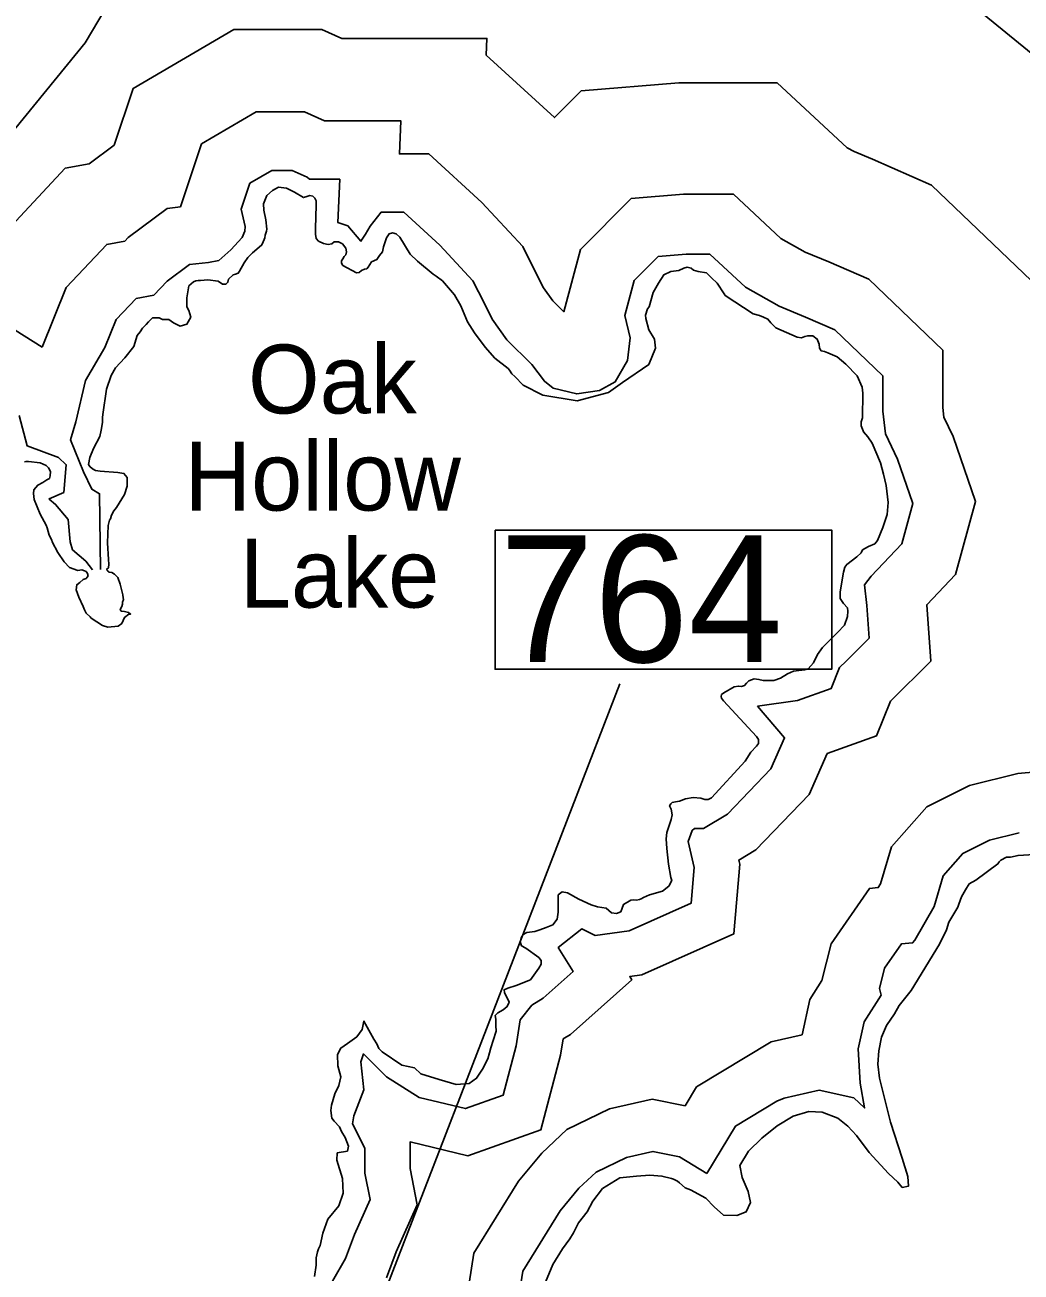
# Model space of a CAD drawing. Extents: x 1662474 to 1856135, y 779280 to 917889.
# Drawn here: x 1704529 to 1707278, y 822946 to 826386 of the extents above; entities that cross this region are included whole.
import ezdxf

# ---------------------------------------------------------------- set-up
doc = ezdxf.new("R2010")
doc.units = 0
for name, color, linetype in [('Exist Hydrographic Lake Shore', 7, 'Continuous'), ('Exist Hydrographic Lake Shore Label', 7, 'Continuous'), ('Old_Level_44', 7, 'Continuous'), ('Scratch_Level_2', 7, 'Continuous')]:
    doc.layers.add(name, color=color, linetype=linetype)

msp = doc.modelspace()

# ---------------------------------------------------------------- linework, layer by layer
at = {"layer": 'Exist Hydrographic Lake Shore'}
for points in [[(1706250.5, 825545.1), (1706266.8, 825519.9), (1706269.1, 825495), (1706251, 825449.6), (1706178.4, 825399.8), (1706139.8, 825372.4), (1706053.4, 825349.6), (1705958.4, 825365.4), (1705903.8, 825392.7), (1705881.2, 825416.8), (1705872.6, 825423.4), (1705866.5, 825434.1), (1705862.9, 825438.3), (1705825.4, 825467.2), (1705799.4, 825497.1), (1705769.8, 825536.5), (1705750.8, 825566.9), (1705732.1, 825611.8), (1705714.6, 825641.8), (1705681.2, 825680.1), (1705663.9, 825693.4), (1705656, 825698.7), (1705612.5, 825734.4), (1705592, 825754.3), (1705563.9, 825800.8), (1705553.1, 825810), (1705543.8, 825812.9), (1705534.2, 825810.2), (1705527.1, 825798.9), (1705519, 825774.2), (1705515.6, 825760.4), (1705507.5, 825749.9), (1705500.6, 825739.4), (1705485.8, 825732.6), (1705480.5, 825725.4), (1705476.5, 825718.4), (1705472.4, 825713.9), (1705465.8, 825712.3), (1705457.6, 825708.9), (1705451, 825703.4), (1705444.5, 825702.6), (1705406.5, 825722.8), (1705402.5, 825729.1), (1705402.5, 825735.9), (1705406.5, 825740.7), (1705410.4, 825747.5), (1705414.6, 825752.2), (1705416.1, 825760.4), (1705414.6, 825770.9), (1705405.4, 825782.7), (1705394.4, 825787.9), (1705382.5, 825787.9), (1705375.8, 825782.9), (1705366, 825781.1), (1705352.6, 825783.2), (1705339.5, 825789.5), (1705332.4, 825796.9), (1705331.1, 825809.4), (1705330.6, 825823.6), (1705330.6, 825836.5), (1705331.6, 825844.9), (1705332.4, 825901.3), (1705328.8, 825908.4), (1705323.2, 825914.2), (1705315.4, 825915.5), (1705307.2, 825913.4), (1705297.5, 825910), (1705273.4, 825924.7), (1705250.5, 825936.5), (1705229, 825938.8), (1705211.8, 825929.9), (1705196.5, 825916), (1705187, 825892.6), (1705188.6, 825875.1), (1705194.1, 825849.1), (1705196.5, 825823.4), (1705195.6, 825817.6), (1705191.8, 825806.3), (1705190.8, 825799.2), (1705184.6, 825783.4), (1705182, 825778.5), (1705156.6, 825758), (1705144.2, 825745.1), (1705134.5, 825730.2), (1705121.1, 825706.8), (1705117.5, 825701.8), (1705110.4, 825698.4), (1705103.5, 825696.6), (1705090.5, 825684.8), (1705089.1, 825676.6), (1705083.6, 825670.9), (1705073.9, 825671.1), (1705062.4, 825679.2), (1705033.5, 825683.2), (1705013.8, 825681.1), (1705006.8, 825681.6), (1705000.4, 825680.6), (1704994.4, 825677.2), (1704981.2, 825666.4), (1704976.2, 825633.6)], [(1706553.9, 824403.7), (1706553.9, 824415.2), (1706548.4, 824423.6), (1706457.1, 824522.1), (1706451.2, 824529.2), (1706450, 824533.6), (1706451.2, 824539.1), (1706458.1, 824544.1), (1706486.5, 824560.4), (1706498.2, 824562.5), (1706506.4, 824561.7), (1706514.9, 824563.8), (1706520.1, 824570.6), (1706526.6, 824576.7), (1706541.9, 824582.2), (1706554.5, 824580.9), (1706566.8, 824577.7), (1706589.1, 824577.4), (1706595.6, 824577.7), (1706614.2, 824583.8), (1706633.2, 824596.4), (1706649.8, 824603.4), (1706680.1, 824606.9), (1706690.9, 824610.2), (1706704.9, 824626.8), (1706716.6, 824649.6), (1706730, 824669.3), (1706758.9, 824697.7), (1706771.8, 824709.8), (1706790.9, 824730.8), (1706798.8, 824754.1), (1706800.1, 824769.3), (1706798.8, 824778.5), (1706788, 824790.1), (1706778.6, 824803.9), (1706778.6, 824822.6), (1706788, 824876.9), (1706792, 824890.1), (1706797.2, 824897.9), (1706824.5, 824918.6), (1706836.4, 824930.2), (1706840.8, 824938.3), (1706856.8, 824947.8), (1706874.1, 824954.9), (1706882.2, 824963.8), (1706896.5, 825000), (1706909, 825035.7), (1706911.6, 825069.3), (1706905.4, 825115.8), (1706898.2, 825147.2), (1706890.1, 825178.5), (1706867.2, 825232.8), (1706855.5, 825250.1), (1706843.1, 825263.8), (1706842.6, 825266.9), (1706837.1, 825280.3), (1706837.1, 825291.4), (1706840.8, 825302.1), (1706841.6, 825370.9), (1706839.2, 825386.9), (1706825.6, 825418.1), (1706794.6, 825450.7), (1706770.5, 825470.4), (1706745, 825481.9), (1706735.5, 825485.3), (1706726.1, 825487.4), (1706721.9, 825494.5), (1706720.6, 825506.1), (1706715.4, 825519.9), (1706703, 825529.1), (1706689.6, 825529.1), (1706681.5, 825527.1), (1706672, 825523.4), (1706659.8, 825524.7), (1706600.9, 825551.2), (1706587.2, 825564.1), (1706579.4, 825574.3), (1706567, 825580.1), (1706556.2, 825584.8), (1706538.8, 825589.5), (1706461.8, 825640.4), (1706458.6, 825644.1), (1706439.2, 825674), (1706424.2, 825689), (1706409.6, 825702.6), (1706386.8, 825706.3), (1706374.4, 825709.7), (1706367.6, 825715.8), (1706356.9, 825717.9), (1706347.4, 825715.8), (1706333.8, 825708.7), (1706311.4, 825706.1), (1706292.2, 825697.1), (1706277.2, 825673.8), (1706262.9, 825648.3), (1706252.1, 825608.7), (1706247.1, 825602.9), (1706241.6, 825585.6), (1706242.6, 825576.4), (1706250.5, 825545.1)], [(1704976.2, 825633.6), (1704976.2, 825608.9), (1704981.2, 825598.2), (1704986.5, 825580.3), (1704976.2, 825560.6), (1704957.1, 825554.9), (1704939.2, 825564.6), (1704926.1, 825574), (1704908.9, 825573.5), (1704899.4, 825578.8), (1704881.5, 825577.9), (1704870.2, 825566.9), (1704863.9, 825559.6), (1704853.4, 825550.1), (1704846.6, 825539.6), (1704838.8, 825529.4), (1704829.2, 825499.5), (1704804.9, 825468), (1704779.4, 825440.2), (1704767.1, 825419.4), (1704753.8, 825381.1), (1704744, 825311.6), (1704743.2, 825303.2), (1704743.2, 825289.2), (1704739.5, 825268.2), (1704735.9, 825251.2), (1704718, 825217.9), (1704707.8, 825193.2), (1704704.6, 825173.8), (1704708.5, 825167.8), (1704715.6, 825161.9), (1704723.8, 825157.5), (1704737.1, 825154.9), (1704785.5, 825151.4), (1704802, 825149.1), (1704811.1, 825137.6), (1704811.1, 825114.2), (1704804.1, 825091.1), (1704781.5, 825055.1), (1704774.1, 825045.9), (1704767.9, 825034.1), (1704764.8, 825024.2), (1704762.6, 825020.5), (1704758.4, 825005.2), (1704756.9, 824958), (1704760, 824911.6), (1704761, 824898.7), (1704760, 824888.8), (1704754.8, 824885.1), (1704756, 824880.9), (1704757.6, 824879), (1704760, 824878.2), (1704761, 824876.7), (1704769.1, 824875.6), (1704776, 824871.1), (1704785.2, 824861.7), (1704792, 824843.3), (1704798.9, 824814.2), (1704800.4, 824805.8), (1704800.6, 824801.1), (1704798.4, 824793.8), (1704798, 824788.8), (1704796, 824781.6), (1704792, 824773.8), (1704794.6, 824769.1), (1704803.9, 824768), (1704814.9, 824765.4), (1704820.4, 824760.9), (1704816.1, 824760.9), (1704803.9, 824752), (1704796, 824735.4), (1704786.5, 824727.3), (1704758.1, 824724.9), (1704743.5, 824729.4), (1704712.2, 824749.4), (1704709.4, 824753.3), (1704698.4, 824763.6), (1704693.4, 824772.4), (1704689.4, 824782.2), (1704677.6, 824807.4), (1704670.5, 824828.4), (1704672.1, 824842), (1704680.2, 824847.8), (1704689.6, 824856.2), (1704698, 824859.3), (1704703.2, 824866.4), (1704701.8, 824873), (1704698, 824878.2), (1704693.6, 824880.1), (1704685.8, 824882.7), (1704674.8, 824881.6), (1704651.9, 824889.8), (1704637.4, 824904.8), (1704619.9, 824931.2), (1704604.6, 824960.1), (1704602.8, 824965.4), (1704596, 824979), (1704590.1, 824998.9), (1704587.2, 825006.8), (1704571.2, 825037)], [(1704571.2, 825037), (1704554.8, 825077.4), (1704552.4, 825093.7), (1704554, 825103.9), (1704564.2, 825117.1), (1704578.1, 825123.9), (1704589.9, 825131), (1704596.8, 825135.4), (1704598.6, 825142.6), (1704599.6, 825154.1), (1704594.1, 825164.3), (1704587.2, 825171.4), (1704571.2, 825178.5), (1704539, 825181.9), (1704531.4, 825181.6), (1704527.5, 825180.9)], [(1706532.1, 824380.3), (1706548.4, 824396.9), (1706553.9, 824403.7)], [(1705376, 823370.1), (1705373.4, 823391.9), (1705375.2, 823406.6), (1705383.9, 823437.8), (1705395.4, 823460.7), (1705400.9, 823484.1), (1705393, 823515.2), (1705391.2, 823546), (1705400.9, 823563.8), (1705419.6, 823576.4), (1705445.2, 823595.1), (1705459.5, 823615.2), (1705464.5, 823638.1), (1705491.5, 823588.2), (1705500.1, 823575.6), (1705505.9, 823562.8), (1705514.9, 823553.1), (1705569.1, 823516.3), (1705604.1, 823509.5), (1705621.9, 823492.9), (1705672, 823476.9), (1705719, 823463.1), (1705755, 823466.2), (1705775.5, 823480.6), (1705792, 823505.3), (1705806.1, 823533.9), (1705811.1, 823550.4), (1705814.6, 823564.4), (1705821.4, 823584.3), (1705829.2, 823610.6), (1705828.2, 823626), (1705828.2, 823643.1), (1705826.6, 823653.6), (1705834.5, 823661.4), (1705848.8, 823669.3), (1705860, 823678.2), (1705865.2, 823690.3), (1705852.1, 823717.4), (1705851.4, 823724.7), (1705861.5, 823729.4), (1705884.4, 823736.2), (1705924.2, 823752), (1705947.1, 823783.8), (1705953.4, 823795.3), (1705953.4, 823805.3), (1705947.1, 823813.9), (1705911.1, 823839.7), (1705899.6, 823846.2), (1705895.9, 823857.2), (1705898.5, 823868.2), (1705903.8, 823876.9), (1705914, 823883), (1705936.4, 823885.6), (1705950.2, 823889.8), (1705967.6, 823896.4), (1705986, 823904.2), (1705998.2, 823919.4), (1706000.9, 823938.6), (1706000.9, 823986.4), (1706011.4, 823995.1), (1706026.4, 823991.9), (1706058.1, 823974.3), (1706091.8, 823958.8), (1706109.4, 823953.8), (1706133, 823949.9), (1706148.1, 823937.3), (1706161.8, 823935.2), (1706173.4, 823939.9), (1706181.2, 823959.9), (1706201.5, 823972.2), (1706209, 823972.8), (1706217.2, 823971.9), (1706224.8, 823973.2), (1706229.8, 823975.6), (1706235.9, 823979.6), (1706252.9, 823986.6), (1706288.6, 823996.4), (1706305.6, 824010), (1706314.2, 824025.8), (1706311.1, 824034.7), (1706305.4, 824071.2), (1706300.1, 824114.8), (1706299.1, 824141.2), (1706300.4, 824158.8), (1706312.5, 824194.8), (1706315.1, 824207.6), (1706312.5, 824222.9), (1706308.2, 824231.8), (1706311.4, 824237.8), (1706315.1, 824241.2), (1706324.5, 824243.3), (1706335.2, 824244.9), (1706351.6, 824251.8), (1706372.9, 824255.1), (1706394.6, 824253.1), (1706405.4, 824249.4), (1706414.5, 824249.4), (1706424.2, 824254.1), (1706517.1, 824354.9), (1706532.1, 824380.3)], [(1707358.9, 824100.8), (1707269.9, 824095.1), (1707248.6, 824090.3), (1707237.6, 824090.3), (1707222.6, 824082.4), (1707218, 824078), (1707214, 824071.9), (1707153.1, 824026.6), (1707135.2, 824016.6), (1707125, 824000.3), (1707113.5, 823980.6), (1707106.1, 823960.7), (1707103.5, 823952.2), (1707089.4, 823929.7), (1707079.1, 823910.8), (1707072.2, 823889.8), (1707053.4, 823850.7), (1706975.1, 823722.9), (1706941.9, 823681.4), (1706929, 823658.3), (1706906.4, 823626.3), (1706893.2, 823594), (1706885.4, 823555.7), (1706882.8, 823519.2), (1706887.8, 823480.6), (1706917.4, 823359.1), (1706950.2, 823259.6), (1706966, 823209.5), (1706967, 823182.4), (1706950.2, 823179.3), (1706937.9, 823194), (1706912.5, 823217.4), (1706858.6, 823275.6)], [(1706858.6, 823275.6), (1706824, 823322.4), (1706799.9, 823348.3), (1706772.5, 823370.6), (1706729.2, 823387.2), (1706692.2, 823389), (1706649.2, 823375.6), (1706605.4, 823348.9), (1706563.1, 823315.6), (1706525.9, 823279.1), (1706501.8, 823239.9), (1706508.2, 823206.4), (1706525, 823167.8), (1706531.1, 823137.6), (1706519.5, 823112.1), (1706494.1, 823102.1), (1706457.1, 823102.9), (1706431.6, 823125.5), (1706408, 823149.9), (1706365.8, 823172.8), (1706351, 823178.5), (1706335.2, 823192.2), (1706329.8, 823196.4), (1706319.2, 823202.4), (1706313.8, 823204.2), (1706286.8, 823210.8), (1706253.6, 823212.9), (1706216.4, 823210.8), (1706170.5, 823206.1), (1706123, 823176.2), (1706096.5, 823141.8), (1706080.8, 823111.9), (1706056.5, 823081.9), (1706043.1, 823054.4), (1706033, 823037.9), (1706013, 823009.5), (1705986.2, 822966.4), (1705965.8, 822918.4)], [(1705328.2, 822933.4), (1705333.2, 822964.6), (1705333.2, 822985.1), (1705336.6, 823001.4), (1705339.5, 823010.3), (1705344, 823018.9), (1705351.4, 823053.3), (1705364.5, 823092.2), (1705395.1, 823128.9), (1705407.5, 823163.3), (1705405.1, 823204.2), (1705390.1, 823254.4), (1705391, 823274.3), (1705419.2, 823279.8), (1705421.9, 823293.5), (1705413, 823317.4), (1705403, 823333.6), (1705397.5, 823346.2), (1705382.5, 823362.2), (1705376, 823370.1)]]:
    msp.add_lwpolyline(points, dxfattribs=at)
at = {"layer": 'Old_Level_44'}
msp.add_line((1706604.2, 823417.4), (1706624.5, 823425.6), dxfattribs=at)
for points in [[(1706416.7, 828453.3), (1706394.4, 828185.5), (1706206.4, 827887), (1705933.6, 827714.4), (1705493.1, 827597.8), (1705428.1, 827536.3), (1705411.4, 827514), (1705562.9, 827305.8), (1705253, 826872.2), (1704944.5, 826583.1), (1704843.4, 826587.3), (1704694.9, 826337.4), (1704445.7, 826032.9), (1704213.1, 825950.9), (1704071.6, 825880.8), (1703834.3, 825734.9), (1703563.6, 825780), (1703448, 825768.5), (1703249, 825751.6), (1703132.7, 825730.4)], [(1708420, 826265.1), (1708349.1, 826265.1), (1708347.7, 826266.3), (1708137.7, 826126.4), (1707570.3, 826203.7), (1707439.7, 826317.9), (1707345.7, 826276.2), (1707041.9, 826524.6), (1706975.9, 826554.3), (1706854.2, 826573), (1706366, 826782.1), (1706321.1, 827321.6), (1706456.4, 827727.4), (1706625.8, 827883.7), (1706744, 828083.1), (1706798.2, 828171.6), (1706646.7, 828238.8), (1706416.7, 828453.3)], [(1704403.4, 825738.6), (1704640.4, 825991.2), (1704706.4, 826003.2), (1704775.3, 826054.9), (1704827.5, 826211.4), (1705105.4, 826373.4), (1705348.8, 826373.4), (1705403.8, 826349), (1705804.1, 826349), (1705802, 826302.9)], [(1705802, 826302.9), (1705990.5, 826130.7), (1706064.5, 826204.7), (1706334, 826227.1), (1706604.9, 826227.1), (1706798.3, 826047.6), (1706817.5, 826036.8), (1706868, 826016), (1707031.1, 825944.7), (1707370, 825620.1), (1707370, 825379.8), (1707375.7, 825367.6), (1707475.1, 825081.9), (1707369.8, 824702.7)], [(1704576.2, 825497.5), (1704643.1, 825662), (1704754.8, 825781), (1704804.8, 825790.1), (1704814.3, 825800.1), (1704921.4, 825880.3), (1704958.1, 825884.7), (1705016, 826058.2), (1705166.8, 826146.2), (1705300.6, 826146.2), (1705355.6, 826121.7), (1705566.5, 826121.7), (1705562.4, 826030.6), (1705643.6, 826030.6)], [(1707268.8, 824321.3), (1707506, 824342.6), (1707961.3, 824686.1), (1708109.9, 824801.9), (1708302.4, 824959.8), (1708172.8, 825192.3), (1708209.9, 825405.7), (1708329.3, 825584.7), (1708508.8, 825729.9), (1708557.8, 825740.4), (1708607.5, 825939), (1708747.4, 826058.9)], [(1705643.6, 826030.6), (1705790.3, 825896.6), (1705902.9, 825775.2), (1705943.9, 825693.3), (1705960.1, 825660.8), (1705985.6, 825625.6), (1706016, 825595.2), (1706061.8, 825766.7), (1706202.4, 825907.3), (1706346.8, 825919.3), (1706484.1, 825919.3), (1706615.4, 825797.4), (1706682.7, 825759.4), (1706747.8, 825732.6), (1706857.6, 825684.6), (1707062.2, 825488.7), (1707062.2, 825330.6), (1707065.2, 825304.4), (1707090.3, 825251.1), (1707152.8, 825071.6), (1707096.9, 824870.7), (1707017.7, 824786.9), (1707028.9, 824631.4), (1706917.8, 824520.4), (1706879.6, 824424.9), (1706743.1, 824376.2)], [(1704737.4, 824884.4), (1704735, 825093.2), (1704714.1, 825105.6), (1704690.4, 825153.5), (1704655, 825241.7), (1704669.9, 825291.5), (1704696, 825405.4), (1704749.7, 825496.1), (1704781.2, 825573.5), (1704836, 825631.9), (1704885.2, 825640.9), (1704921.7, 825679.1), (1704983.3, 825725.3), (1705035.2, 825731.4), (1705063.8, 825736.8), (1705097.5, 825765.9), (1705128.4, 825800.2), (1705135.7, 825817), (1705136.6, 825830.6), (1705126, 825878.5), (1705149.7, 825949.6), (1705210.4, 825984.9), (1705266.4, 825984.9), (1705307.8, 825966.5), (1705314.1, 825960.5), (1705397.9, 825960.5), (1705392.6, 825841.1), (1705420.6, 825832.5), (1705456.3, 825789.8), (1705469.2, 825809.2), (1705481.6, 825831.5), (1705512, 825869.4), (1705574.9, 825869.4)], [(1705574.9, 825869.4), (1705673.7, 825779.1), (1705765.5, 825680.1), (1705796, 825619.3), (1705818.3, 825574.7), (1705859.4, 825517.9), (1705928, 825449.3), (1705962.5, 825403.4), (1705986.5, 825384.7), (1706051.9, 825368.4), (1706114.9, 825378.3), (1706158.1, 825401.4), (1706192.4, 825460.5), (1706198.9, 825522.8), (1706184.5, 825585.2), (1706210.1, 825681.2), (1706276.5, 825747.5), (1706353.7, 825753.9), (1706419.2, 825753.9), (1706517.2, 825662.9), (1706610.3, 825610.3), (1706683.2, 825580.4), (1706764.4, 825544.8), (1706896.8, 825418.1), (1706896.8, 825320.9), (1706904.2, 825258.3), (1706937, 825188.6), (1706979.6, 825066.1), (1706948.6, 824954.4), (1706864.6, 824865.6), (1706845.7, 824842), (1706852.1, 824785), (1706858.5, 824694.9), (1706795.1, 824631.6), (1706776.9, 824613.4), (1706753.8, 824555.6), (1706660.9, 824522.4), (1706550.4, 824507.4)], [(1703634.7, 825411.3), (1703770.8, 825486.9), (1703944.7, 825525.2), (1704085.8, 825495.8), (1704159.6, 825484), (1704204.3, 825485.8), (1704258.9, 825504.7), (1704330.4, 825544.4), (1704502.5, 825544.4), (1704576.2, 825497.5)], [(1704513.4, 825308.9), (1704535.3, 825225.1), (1704621.7, 825192.6), (1704643.1, 825173.2), (1704636.1, 825096.6), (1704595.5, 825078.9), (1704595.7, 825078.2), (1704613.7, 825063.5), (1704648.5, 825021.8), (1704653.9, 824960.1), (1704659.9, 824938.5), (1704696.9, 824907.1), (1704715.5, 824883.2)], [(1706550.4, 824507.4), (1706625.7, 824419.6), (1706587.6, 824334.1), (1706467.7, 824209.3), (1706401.6, 824169.6), (1706376.5, 824169.6), (1706370.5, 824164.3), (1706359.6, 824133.9), (1706375.6, 824062.1), (1706367.3, 823963.2), (1706196.9, 823886.8), (1706102.6, 823874.3), (1706065.5, 823892.8), (1706000.8, 823841.1), (1706041.9, 823775.3), (1705959.1, 823701.7), (1705928.2, 823682.4), (1705895.9, 823641.3), (1705884.6, 823569.6), (1705848.5, 823433.7), (1705744.7, 823396.6), (1705616.9, 823427.3), (1705526.5, 823484.3), (1705463.1, 823547.6), (1705455.9, 823526), (1705464, 823448.8), (1705437, 823376.8), (1705433.3, 823354.6), (1705466.9, 823287.5), (1705466.9, 823219.1), (1705481.5, 823145.7), (1705438.2, 823049.5), (1705413.3, 822983), (1705378.1, 822920.5)], [(1706743.1, 824376.2), (1706692.9, 824263.3), (1706546.3, 824110.7), (1706499, 824082.4), (1706501.6, 824070.7), (1706485.7, 823879.3), (1706231.4, 823765.4), (1706198.2, 823761), (1706203.8, 823752), (1706034.2, 823601.3), (1706014.1, 823588.8), (1706007, 823543.8), (1705952.4, 823338.1), (1705751.7, 823266.5), (1705591.8, 823304.8), (1705591.8, 823231.5), (1705611.9, 823131), (1705553.8, 823001.9), (1705526.8, 822930.1)], [(1706588.9, 823581.3), (1706673.9, 823600.7), (1706694.9, 823697.5), (1706728.5, 823750.6), (1706753.7, 823851.2), (1706859.7, 824004.2), (1706884, 824006.3), (1706890.3, 824017.3), (1706920.1, 824118.5), (1707017.9, 824229.2), (1707135.7, 824288), (1707268.8, 824321.3)], [(1706624.5, 823425.6), (1706720.6, 823447.5), (1706816.7, 823426.2), (1706846.3, 823398.5), (1706834.3, 823467.4), (1706828.9, 823561.7), (1706845, 823636), (1706891.8, 823709.9), (1706887.6, 823728.2), (1706901.6, 823784.2), (1706948.1, 823851.3), (1706978.7, 823853.9), (1706984.7, 823861.4), (1707038.2, 823953.9), (1707063.4, 824039.3), (1707117.1, 824100.2), (1707191.4, 824137.3), (1707272.8, 824157.6)], [(1706350.9, 823404.7), (1706382.4, 823456.5), (1706588.9, 823581.3)], [(1704860.2, 821486.9), (1704826.7, 821637.7), (1704852.1, 821790.2), (1704900.1, 821891.6), (1704993.5, 821988.6), (1705107.3, 822073.9), (1705250.8, 822091.8), (1705290.4, 822084.3), (1705294.3, 822104), (1705350.8, 822204), (1705417.1, 822281.7), (1705436.1, 822351.2), (1705492.1, 822519), (1705611.7, 822644.7), (1705755.4, 822915), (1705768, 822998.2), (1705891, 823197), (1705955.1, 823273.9), (1706024.9, 823339.3), (1706142.4, 823396), (1706260.3, 823422.8), (1706350.9, 823404.7)], [(1706410.6, 823217.4), (1706490.2, 823348.5), (1706604.2, 823417.4)], [(1705887, 822842.3), (1705903.1, 822948.5), (1706005.7, 823114.4), (1706057.8, 823176.9), (1706105.6, 823221.7), (1706189.3, 823262.1), (1706262.2, 823278.7), (1706335.1, 823264.1), (1706410.6, 823217.4)]]:
    msp.add_lwpolyline(points, dxfattribs=at)
at = {"layer": 'Scratch_Level_2'}
msp.add_line((1705349.4, 822445.8), (1706171, 824568.2), dxfattribs=at)
msp.add_lwpolyline([(1705826.7, 824992.8), (1706755.7, 824992.8), (1706755.7, 824608.7), (1705826.7, 824608.7)], close=True, dxfattribs=at)

# ---------------------------------------------------------------- texts
at = {"layer": 'Exist Hydrographic Lake Shore Label'}
for s, p in [('Oak', (1705144.7, 825314.5)), ('Hollow', (1704969.7, 825046.7)), ('Lake', (1705121.8, 824779))]:
    msp.add_text(s, height=190, dxfattribs=at).set_placement(p)
at = {"layer": 'Scratch_Level_2'}
msp.add_text('764', height=350, dxfattribs=at).set_placement((1705839.2, 824628.5))

doc.saveas('drawing.dxf')
